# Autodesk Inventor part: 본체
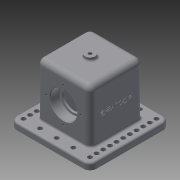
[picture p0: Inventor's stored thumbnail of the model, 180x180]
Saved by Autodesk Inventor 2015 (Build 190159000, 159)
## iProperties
Created: 2018-11
Part Number: 본체
Material: 일반
Document SubType Name: Modeling
Designer: now
Density: 1 g/cm^3
Appearance: 기본값
Mass: 376.663 g
Surface Area: 777.082 cm^2
Volume: 376.663 cm^3
Author: now
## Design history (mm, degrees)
sketch "스케치1"
  geometry: L1 (-60, 60)-(60, 60); L2 (60, 60)-(60, -60); L3 (60, -60)-(-60, -60); L4 (-60, -60)-(-60, 60); L5 (-60, 60)-(60, -60); L6 (60, 60)-(-60, -60); 1 further point
  constraints: 12 end point, 2 midpoint, 2 parallel, 1 horizontal, 1 perpendicular
  dimensions: "d0" = 120 distance of L1.start L1.end; "d1" = 120 distance of L3.end L1.start
extrude "돌출1" new body sketch "스케치1" distance "d2" = 10; taper "d3" = 0 deg
sketch "스케치2"
  geometry: L1 (-40, 40)-(40, 40); L2 (40, 40)-(40, -40); L3 (40, -40)-(-40, -40); L4 (-40, -40)-(-40, 40); L5 (-40, 40)-(40, -40); L6 (40, 40)-(-40, -40); 1 further point
  constraints: 12 end point, 2 midpoint, 2 parallel, 1 horizontal, 1 perpendicular
  dimensions: "d4" = 80 distance of L1.start L1.end; "d5" = 80 distance of L3.end L1.start
extrude "돌출2" join sketch "스케치2" distance "d6" = 80; taper "d7" = 0 deg
sketch "스케치3"
  geometry: L1 (-30, -23)-(30, -23); L2 (30, -23)-(30, 23); L3 (30, 23)-(-30, 23); L4 (-30, 23)-(-30, -23); L5 (-30, -23)-(30, 23); L6 (30, -23)-(-30, 23); 1 further point
  constraints: 12 end point, 2 midpoint, 2 parallel, 1 horizontal, 1 perpendicular
  dimensions: "d8" = 46 distance of L3.end L1.start; "d9" = 60 distance of L1.start L1.end
extrude "돌출3" cut sketch "스케치3" distance "d10" = 80; taper "d11" = 0 deg
sketch "스케치4"
  geometry: L1 (-20, -10)-(-20, 0) reference; L2 (-20, 0)-(0, 0) reference; L3 (0, 0)-(0, 80) reference; L4 (0, 80)-(80, 80) reference; L5 (80, 80)-(80, 0) reference; L6 (80, 0)-(100, 0) reference; L7 (100, 0)-(100, -10) reference; L8 (100, -10)-(-20, -10) reference; L9 (0, 0)-(80, 0) reference; C1 r 20 at (40, 38); 2 further points
  constraints: 1 centre point, 1 midpoint, 1 vertical alignment
  dimensions: "d12" = 40 diameter of C1; "d13" = 48 distance from line of L8 C1.centre
extrude "돌출4" cut sketch "스케치4" distance "d14" = 14; taper "d15" = 0 deg
sketch "스케치5"
  geometry: C1 r 20 at (0, 0) reference; C2 r 16.5 at (0, 0); 1 further point
  constraints: 1 centre point, 1 coincident
  dimensions: "d16" = 33 diameter of C2
extrude "돌출5" cut sketch "스케치5" distance "d17" = 3; taper "d18" = 0 deg
sketch "스케치6"
  geometry: L1 (-20, -10)-(-20, 0) reference; L2 (-20, 0)-(0, 0) reference; L3 (0, 0)-(0, 80) reference; L4 (0, 80)-(80, 80) reference; L5 (80, 80)-(80, 0) reference; L6 (80, 0)-(100, 0) reference; L7 (100, 0)-(100, -10) reference; L8 (100, -10)-(-20, -10) reference; L9 (0, 0)-(80, 0) reference; C1 r 20 at (40, 38) reference; C2 r 20 at (40, 38) reference; 2 further points
  constraints: 1 vertical alignment
  dimensions: "d19" = 26 distance of C1.centre point (40, 64)
hole "구멍1" sketch "스케치6" at (40, 64) diameter "d20" = 3.242; stored, may be unused: countersink angle "d24" = 90 deg, drill point angle "d26" = 118 deg; dims "d21" = 8, "d22" = 4, "d23" = 2, "d25" = 10
node "작업 평면1"
sketch "스케치7"
  geometry: C1 r 7.5 at (0, 0); 1 further point
  constraints: 1 centre point, 1 coincident
  dimensions: "d31" = 15 diameter of C1
extrude "돌출6" join sketch "스케치7" stored distance "d32" = 0; taper "d33" = 0 deg
sketch "스케치8"
  geometry: C1 r 7.5 at (0, 0) reference
hole "구멍2" sketch "스케치8" at (0, 0) diameter "d34" = 4.917; stored, may be unused: countersink angle "d38" = 90 deg, drill point angle "d40" = 0 deg; dims "d35" = 12, "d36" = 4, "d37" = 2, "d39" = 30
node "작업 평면2"
sketch "스케치10"
  geometry: L1 (60, 0)-(-60, 0) reference; 3 further points
  constraints: 1 midpoint, 1 vertical alignment, 1 other
  dimensions: "d42" = 48 distance from line of L1 point (0, 48)
feature "엠보싱1" sketch "스케치10" dims "d0" = 120, "d1" = 120, "d8" = 46, "d9" = 60, "d43" = 0.5, "d44" = 0
fillet "모깎기1" dims "d45" = 10
sketch "스케치12"
  geometry: A1 r 10 centre (50, -50) between (50, -60) and (60, -50) reference; 1 further point
hole "구멍3" sketch "스케치12" at (50, -50) diameter "d46" = 6.6; stored, may be unused: countersink angle "d50" = 90 deg, drill point angle "d52" = 0 deg; dims "d47" = 12, "d48" = 4, "d49" = 2, "d51" = 30
fillet "모깎기2" dims "d59" = 3
fillet "모깎기3" dims "d60" = 8
fillet "모깎기4" dims "d61" = 8
chamfer "모따기1" distance "d62" = 1; stored, may be unused: second distance "d63" = 2, angle "d64" = 45 deg
fillet "모깎기5" dims "d65" = 0.6
fillet "모깎기6" dims "d66" = 3
fillet "모깎기7" dims "d67" = 3
fillet "모깎기8" dims "d68" = 3
node "솔리드1"
pattern_circular "원형 패턴1" dims angle "d28" = 360 deg
mirror "대칭1"
mirror "대칭2"
pattern_linear "직사각형 패턴1" dims "d55" = 10
pattern_linear "직사각형 패턴2" dims "d58" = 25
mirror "대칭3"
mirror "대칭4"
node "절단 모서리 투영1"
node "절단 모서리 투영2"
other parameters: "d30" = 95, "d41" = 58
